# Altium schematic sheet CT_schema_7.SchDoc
size 402 x 220 mm
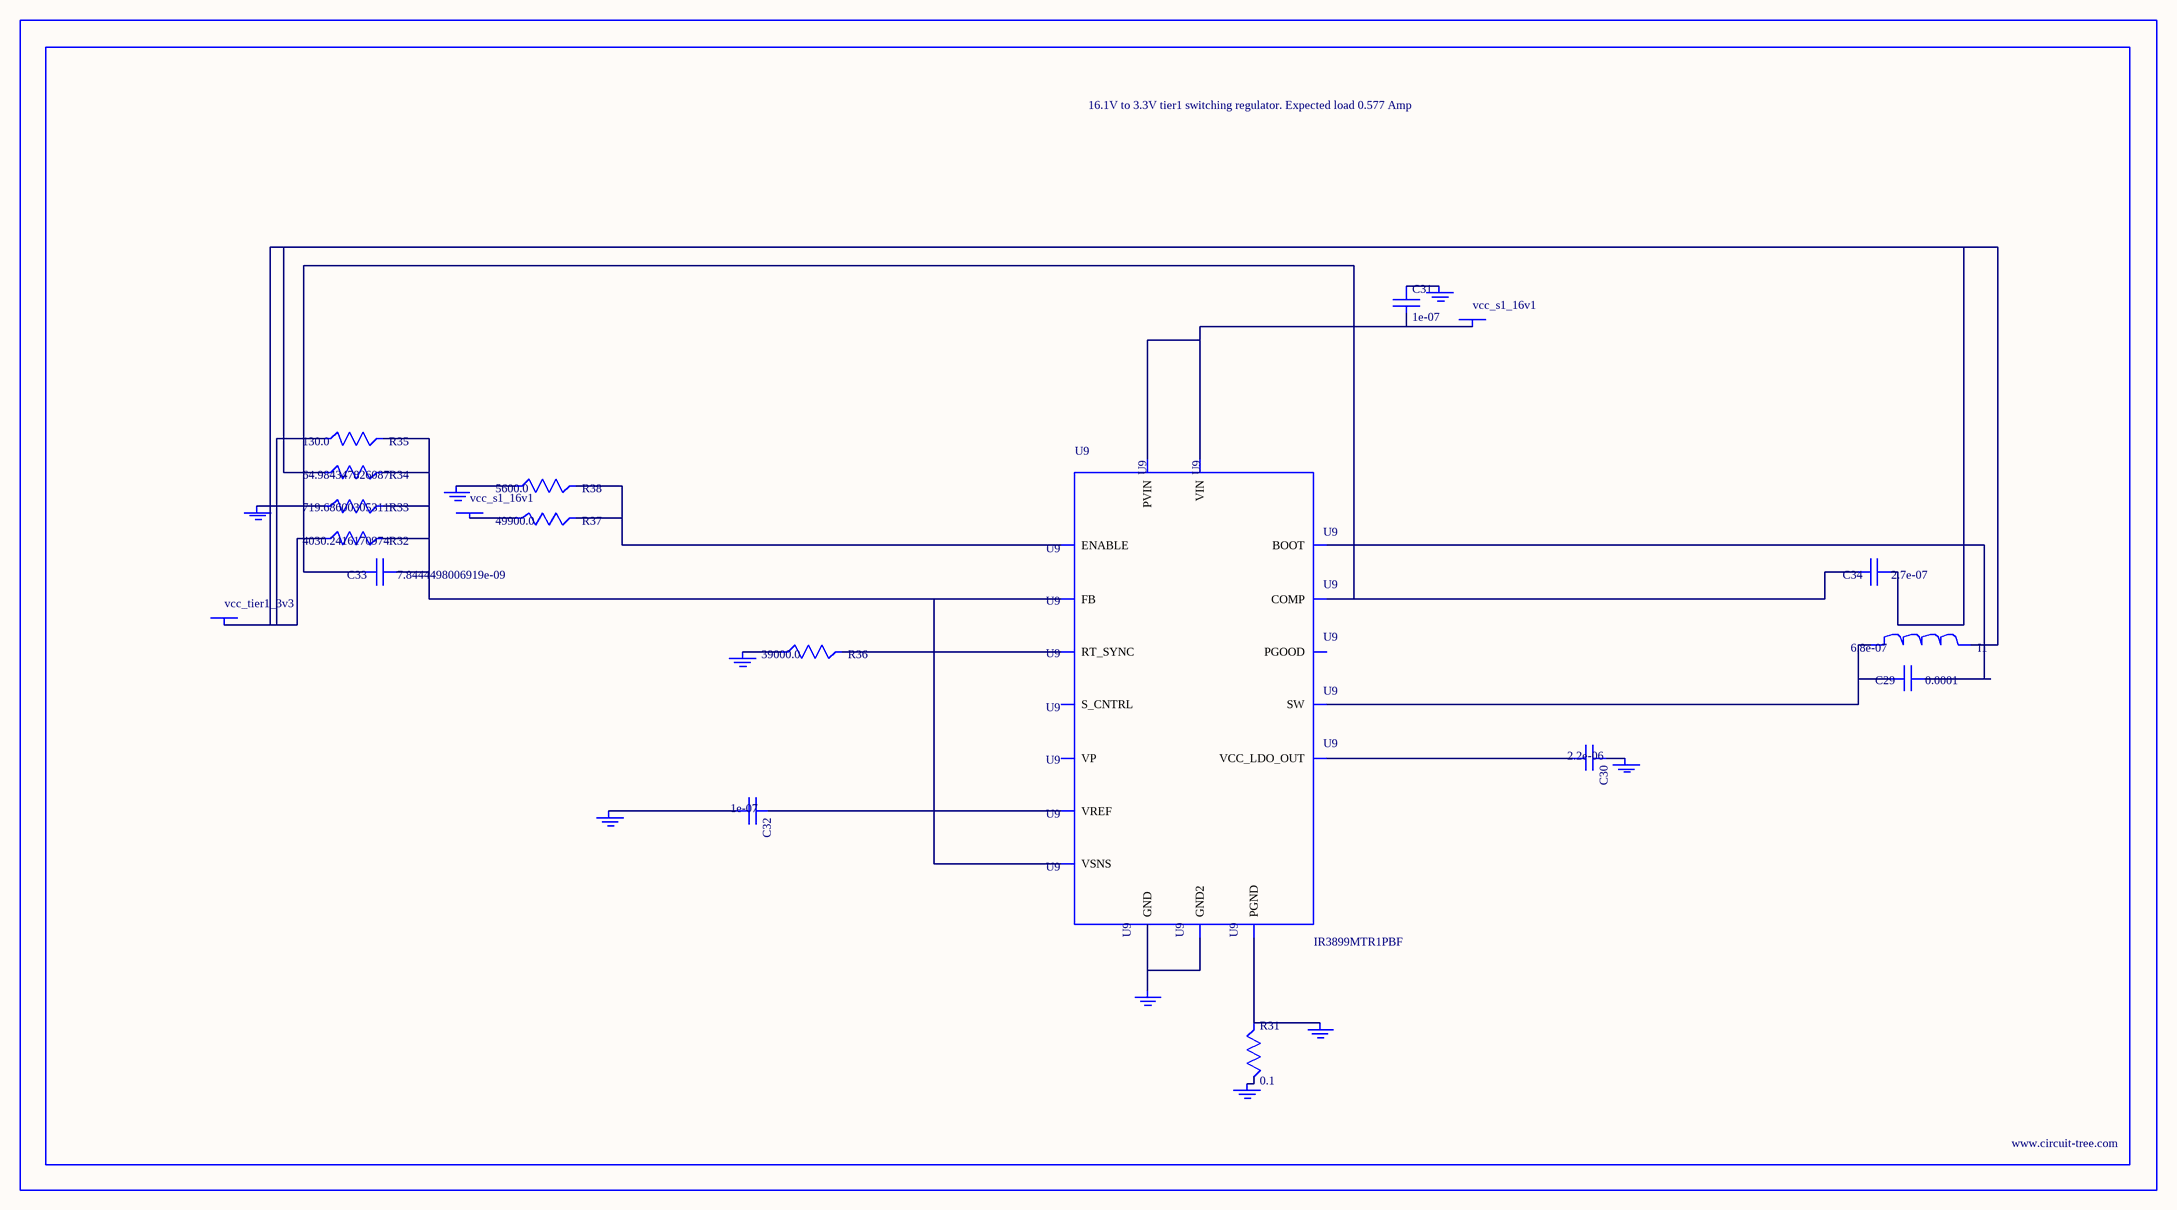
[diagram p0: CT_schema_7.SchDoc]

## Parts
BORDER6  (no value)
C29  0.0001  [C1210]
C30  2.2e-06  [C0603]
C31  1e-07  [C0402]
C32  1e-07  [C0402]
C33  7.8444498006919e-09  [R0603]
C34  2.7e-07  [C0603]
GND_INSTANCE_6_0  (no value)
GND_INSTANCE_6_1  (no value)
GND_INSTANCE_6_2  (no value)
GND_INSTANCE_6_3  (no value)
GND_INSTANCE_6_4  (no value)
GND_INSTANCE_6_5  (no value)
GND_INSTANCE_6_6  (no value)
GND_INSTANCE_6_7  (no value)
GND_INSTANCE_6_8  (no value)
I1  6.8e-07  [IND25X25CZ]
POWER_INSTANCE_6_0  vcc_s1_16v1
POWER_INSTANCE_6_1  vcc_s1_16v1
POWER_INSTANCE_6_2  vcc_tier1_3v3
R31  0.1  [R0603]
R32  4030.2416170974  [R0603]
R33  719.68600305311  [R0603]
R34  64.984347826087  [R0603]
R35  130.0  [R0603]
R36  39000.0  [R0603]
R37  49900.0  [R0603]
R38  5600.0  [R0603]
U9  IR3899MTR1PBF  [IR3899MTR1PBF]

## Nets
NetC29_1: C29.1 U9.14(BOOT)
NetC29_2: C29.2 I1.1 U9.12(SW)
NetC30_1: C30.1 GND_INSTANCE_6_4.0(GND)
NetC30_2: C30.2 U9.10(VCC_LDO_OUT)
NetC31_1: C31.1 GND_INSTANCE_6_3.0(GND)
NetC31_2: C31.2 POWER_INSTANCE_6_0.0(PWR) U9.9(VIN) U9.13(PVIN)
NetC32_1: C32.1 U9.2(VREF)
NetC32_2: C32.2 GND_INSTANCE_6_1.0(GND)
NetC33_1: C33.1 R32.2 R33.2 R34.2 R35.2 U9.1(FB) U9.8(VSNS)
NetC33_2: C33.2 C34.2 U9.3(COMP)
NetC34_1: C34.1 I1.2 POWER_INSTANCE_6_2.0(PWR) R32.1 R34.1 R35.1
NetGND_INSTANCE_6_0_0: GND_INSTANCE_6_0.0(GND) R33.1
NetGND_INSTANCE_6_2_0: GND_INSTANCE_6_2.0(GND) R36.1
NetGND_INSTANCE_6_5_0: GND_INSTANCE_6_5.0(GND) R31.2
NetGND_INSTANCE_6_6_0: GND_INSTANCE_6_6.0(GND) R31.1 U9.11(PGND)
NetGND_INSTANCE_6_7_0: GND_INSTANCE_6_7.0(GND) R38.1
NetGND_INSTANCE_6_8_0: GND_INSTANCE_6_8.0(GND) U9.4(GND) U9.17(GND2)
NetPOWER_INSTANCE_6_1_0: POWER_INSTANCE_6_1.0(PWR) R37.1
NetR36_2: R36.2 U9.5(RT_SYNC)
NetR37_2: R37.2 R38.2 U9.15(ENABLE)

Not connected (* = marked no-connect by the designer): U9 6(S_CNTRL) 7(PGOOD) 16(VP)

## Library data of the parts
BORDER6 = BORDER_PAGE6
C29 = GRM32ER61A107ME20L
C30 = C0603C225K8RACTU
C31 C32 = C0402C104K3RACTU
C33 = C33
C34 = C0603C274K3RAC
GND_INSTANCE_6_0-GND_INSTANCE_6_8 = GND
I1 = IHLP2525CZERR68M01
POWER_INSTANCE_6_0-POWER_INSTANCE_6_2 = PWR
R31 = ERJ-3RSFR10V
R32 = R32
R33 = R33
R34 = R34
R35 = RC0603JR-07130RL
R36 = RC0603JR-0739KL
R37 = RC0603FR-0749K9
R38 = RC0603JR-075K6L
